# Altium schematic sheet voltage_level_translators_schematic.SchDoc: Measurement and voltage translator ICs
size A2; DocumentNumber: 4; SheetNumber: 4; SheetTotal: 8
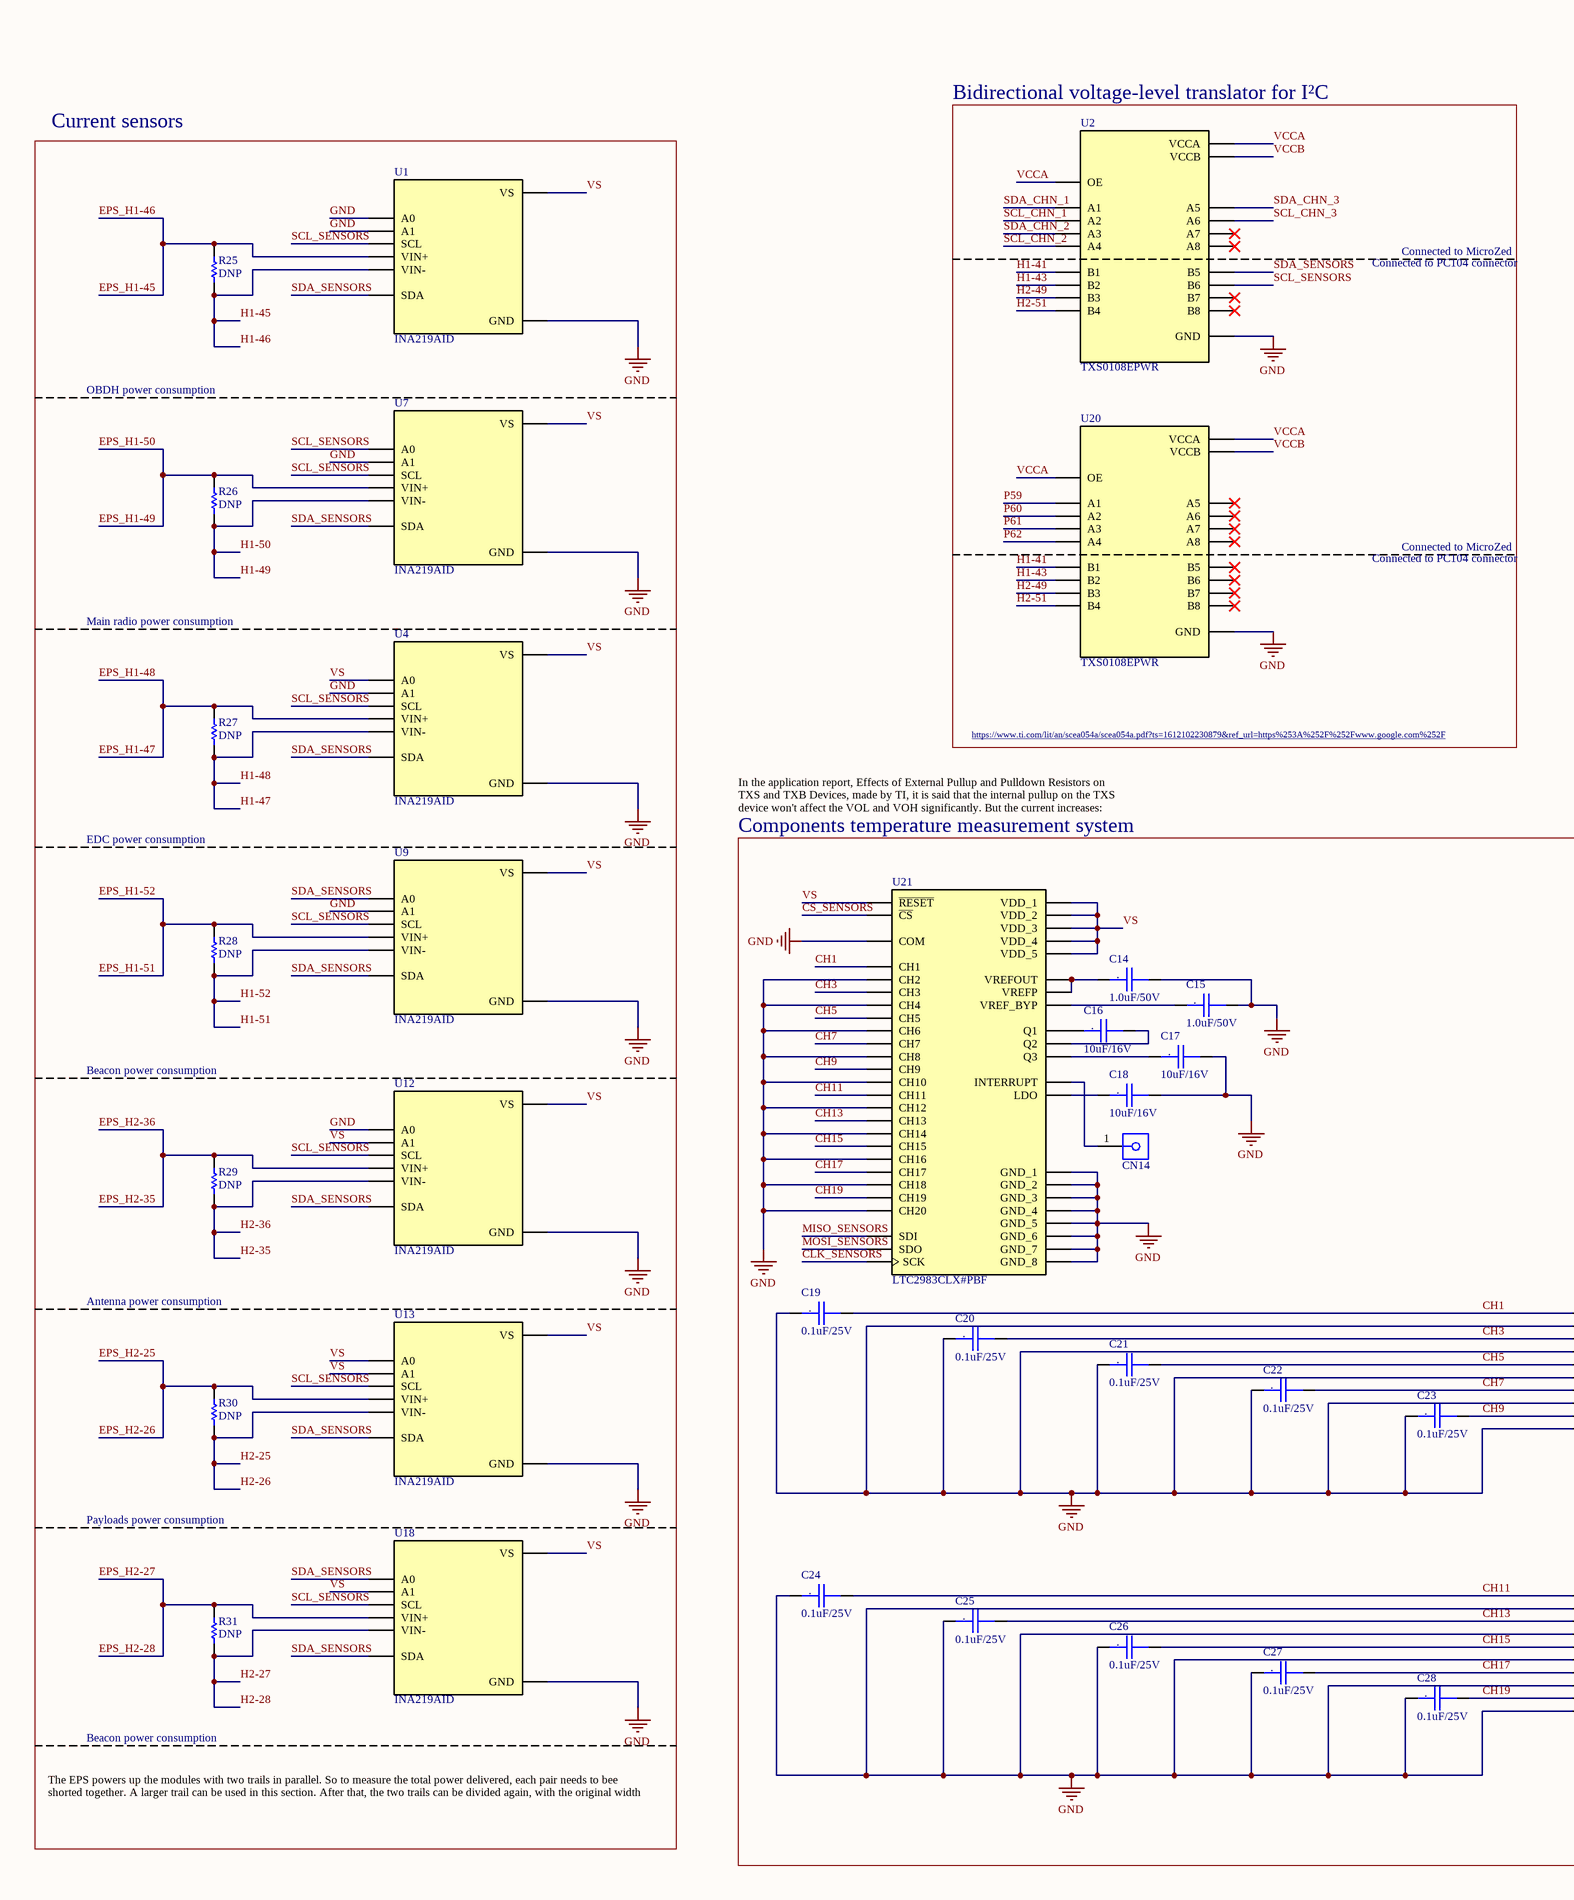
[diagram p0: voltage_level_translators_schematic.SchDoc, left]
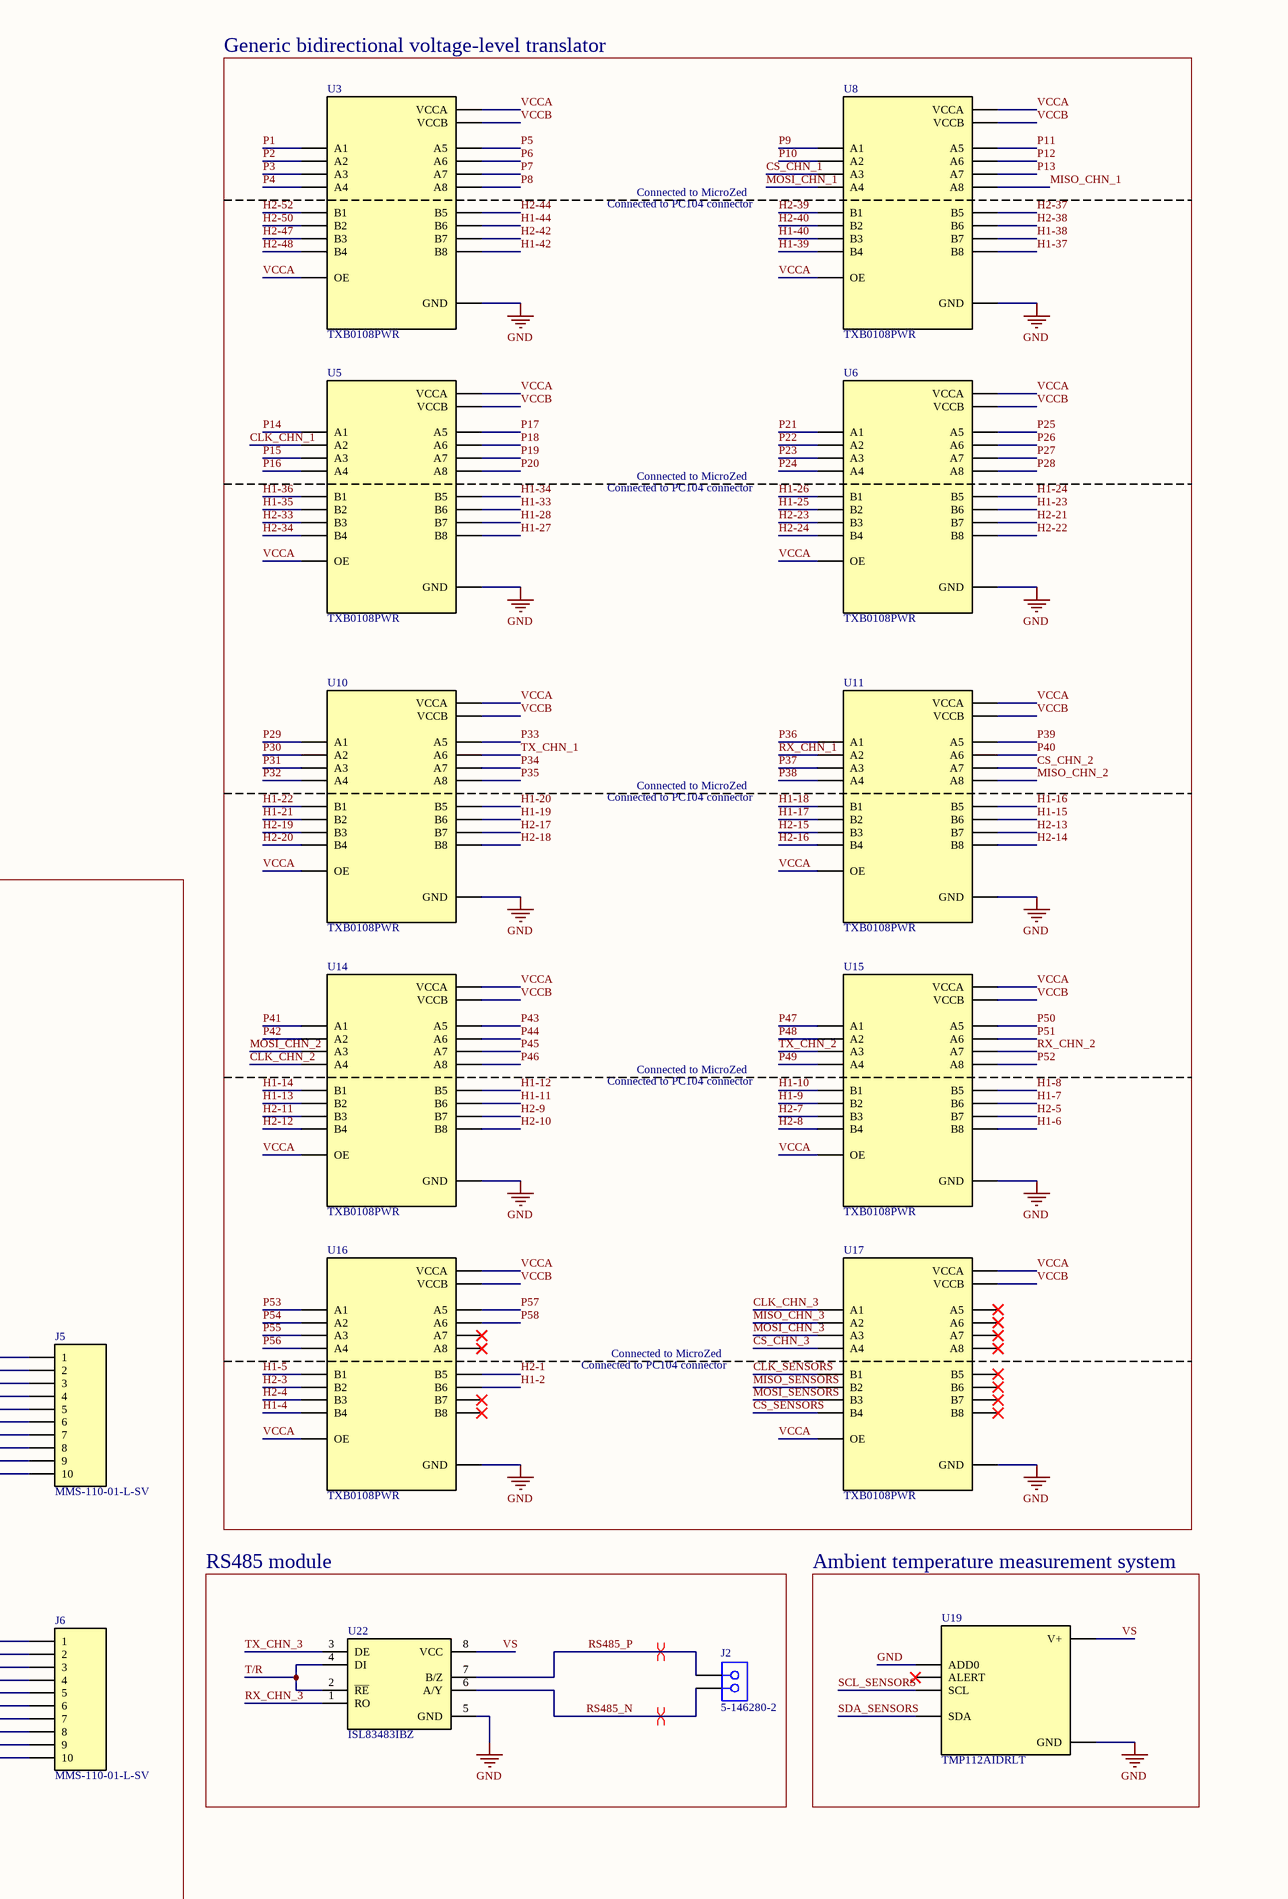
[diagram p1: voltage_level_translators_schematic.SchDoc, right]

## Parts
C14  1.0uF/50V  [CC0805]
C15  1.0uF/50V  [CC0805]
C16  10uF/16V  [CC1210]
C17  10uF/16V  [CC1210]
C18  10uF/16V  [CC1210]
C19  0.1uF/25V  [CC0805]
C20  0.1uF/25V  [CC0805]
C21  0.1uF/25V  [CC0805]
C22  0.1uF/25V  [CC0805]
C23  0.1uF/25V  [CC0805]
C24  0.1uF/25V  [CC0805]
C25  0.1uF/25V  [CC0805]
C26  0.1uF/25V  [CC0805]
C27  0.1uF/25V  [CC0805]
C28  0.1uF/25V  [CC0805]
CN14  TSW-101-05-T-S  [PIN BAR 1 2.54mm 180 GRAUS - Hide]  (value not drawn)
J2  5-146280-2  [PIN BAR 2 2.54mm 180 GRAUS]
J5  MMS-110-01-L-SV  [SAMTEC_MMS-110-01-L-SV]
J6  MMS-110-01-L-SV  [SAMTEC_MMS-110-01-L-SV]
R25  DNP  [0805]
R26  DNP  [0805]
R27  DNP  [0805]
R28  DNP  [0805]
R29  DNP  [0805]
R30  DNP  [0805]
R31  DNP  [0805]
U1  INA219AID  [SOIC127P599X175-8N]
U2  TXS0108EPWR  [SOP65P640X120-20N]
U3  TXB0108PWR  [SOP65P640X120-20N]
U4  INA219AID  [SOIC127P599X175-8N]
U5  TXB0108PWR  [SOP65P640X120-20N]
U6  TXB0108PWR  [SOP65P640X120-20N]
U7  INA219AID  [SOIC127P599X175-8N]
U8  TXB0108PWR  [SOP65P640X120-20N]
U9  INA219AID  [SOIC127P599X175-8N]
U10  TXB0108PWR  [SOP65P640X120-20N]
U11  TXB0108PWR  [SOP65P640X120-20N]
U12  INA219AID  [SOIC127P599X175-8N]
U13  INA219AID  [SOIC127P599X175-8N]
U14  TXB0108PWR  [SOP65P640X120-20N]
U15  TXB0108PWR  [SOP65P640X120-20N]
U16  TXB0108PWR  [SOP65P640X120-20N]
U17  TXB0108PWR  [SOP65P640X120-20N]
U18  INA219AID  [SOIC127P599X175-8N]
U19  TMP112AIDRLT  [SOT50P160X60-6N]
U20  TXS0108EPWR  [SOP65P640X120-20N]
U21  LTC2983CLX#PBF  [QFP50P900X900X160-48N]
U22  ISL83483IBZ  [SOIC127P600X175-8N]

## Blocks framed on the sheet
Generic bidirectional voltage-level translator: U3 U5 U6 U8 U10 U11 U14-U17
Bidirectional voltage-level translator for I²C: U2 U20
Current sensors: R25-R31 U1 U4 U7 U9 U12 U13 U18
Components temperature measurement system: C14-C28 CN14 J5 J6 U21
RS485 module: J2 U22
Ambient temperature measurement system: U19

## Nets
GND: C14.2 C15.2 C17.2 C18.2 C19.1 C20.1 C21.1 C22.1 C23.1 C24.1 C25.1 C26.1 C27.1 C28.1 J5.2 J5.4 J5.6 J5.8 J5.10 J6.2 J6.4 J6.6 J6.8 J6.10 U1.1(A1) U1.2(A0) U1.6(GND) U2.11(GND) U3.11(GND) U4.1(A1) U4.6(GND) U5.11(GND) U6.11(GND) U7.1(A1) U7.6(GND) U8.11(GND) U9.1(A1) U9.6(GND) U10.11(GND) U11.11(GND) U12.2(A0) U12.6(GND) U13.6(GND) U14.11(GND) U15.11(GND) U16.11(GND) U17.11(GND) U18.6(GND) U19.2(GND) U19.4(ADD0) U20.11(GND) U21.1(GND_1) U21.3(GND_2) U21.5(GND_3) U21.7(GND_4) U21.9(GND_5) U21.12(GND_6) U21.15(GND_7) U21.17(CH2) U21.19(CH4) U21.21(CH6) U21.23(CH8) U21.25(CH10) U21.27(CH12) U21.29(CH14) U21.31(CH16) U21.33(CH18) U21.35(CH20) U21.36(COM) U21.44(GND_8) U22.5(GND)
CH1: C19.2 J5.1 U21.16(CH1)
CH3: C20.2 J5.3 U21.18(CH3)
CH5: C21.2 J5.5 U21.20(CH5)
CH7: C22.2 J5.7 U21.22(CH7)
CH9: C23.2 J5.9 U21.24(CH9)
CH11: C24.2 J6.1 U21.26(CH11)
CH13: C25.2 J6.3 U21.28(CH13)
CH15: C26.2 J6.5 U21.30(CH15)
CH17: C27.2 J6.7 U21.32(CH17)
CH19: C28.2 J6.9 U21.34(CH19)
CLK_CHN_1: U5.3(A2)
CLK_CHN_2: U14.5(A4)
CLK_CHN_3: U17.1(A1)
CLK_SENSORS: U17.20(B1) U21.38(SCK)
CS_CHN_1: U8.4(A3)
CS_CHN_2: U11.8(A7)
CS_CHN_3: U17.5(A4)
CS_SENSORS: U17.16(B4) U21.41(~{CS})
EPS_H1-45: R25.1 U1.8(VIN+)  [also labelled EPS_H1-46]
EPS_H1-47: R27.1 U4.8(VIN+)  [also labelled EPS_H1-48]
EPS_H1-49: R26.1 U7.8(VIN+)  [also labelled EPS_H1-50]
EPS_H1-51: R28.1 U9.8(VIN+)  [also labelled EPS_H1-52]
EPS_H2-25: R30.1 U13.8(VIN+)  [also labelled EPS_H2-26]
EPS_H2-27: R31.1 U18.8(VIN+)  [also labelled EPS_H2-28]
EPS_H2-35: R29.1 U12.8(VIN+)  [also labelled EPS_H2-36]
H1-2: U16.14(B6)
H1-4: U16.16(B4)
H1-5: U16.20(B1)
H1-6: U15.12(B8)
H1-7: U15.14(B6)
H1-8: U15.15(B5)
H1-9: U15.18(B2)
H1-10: U15.20(B1)
H1-11: U14.14(B6)
H1-12: U14.15(B5)
H1-13: U14.18(B2)
H1-14: U14.20(B1)
H1-15: U11.14(B6)
H1-16: U11.15(B5)
H1-17: U11.18(B2)
H1-18: U11.20(B1)
H1-19: U10.14(B6)
H1-20: U10.15(B5)
H1-21: U10.18(B2)
H1-22: U10.20(B1)
H1-23: U6.14(B6)
H1-24: U6.15(B5)
H1-25: U6.18(B2)
H1-26: U6.20(B1)
H1-27: U5.12(B8)
H1-28: U5.13(B7)
H1-33: U5.14(B6)
H1-34: U5.15(B5)
H1-35: U5.18(B2)
H1-36: U5.20(B1)
H1-37: U8.12(B8)
H1-38: U8.13(B7)
H1-39: U8.16(B4)
H1-40: U8.17(B3)
H1-41: U2.20(B1) U20.20(B1)
H1-42: U3.12(B8)
H1-43: U2.18(B2) U20.18(B2)
H1-44: U3.14(B6)
H1-45: R25.2 U1.7(VIN-)  [also labelled H1-46]
H1-47: R27.2 U4.7(VIN-)  [also labelled H1-48]
H1-49: R26.2 U7.7(VIN-)  [also labelled H1-50]
H1-51: R28.2 U9.7(VIN-)  [also labelled H1-52]
H2-1: U16.15(B5)
H2-3: U16.18(B2)
H2-4: U16.17(B3)
H2-5: U15.13(B7)
H2-7: U15.17(B3)
H2-8: U15.16(B4)
H2-9: U14.13(B7)
H2-10: U14.12(B8)
H2-11: U14.17(B3)
H2-12: U14.16(B4)
H2-13: U11.13(B7)
H2-14: U11.12(B8)
H2-15: U11.17(B3)
H2-16: U11.16(B4)
H2-17: U10.13(B7)
H2-18: U10.12(B8)
H2-19: U10.17(B3)
H2-20: U10.16(B4)
H2-21: U6.13(B7)
H2-22: U6.12(B8)
H2-23: U6.17(B3)
H2-24: U6.16(B4)
H2-25: R30.2 U13.7(VIN-)  [also labelled H2-26]
H2-27: R31.2 U18.7(VIN-)  [also labelled H2-28]
H2-33: U5.17(B3)
H2-34: U5.16(B4)
H2-35: R29.2 U12.7(VIN-)  [also labelled H2-36]
H2-37: U8.15(B5)
H2-38: U8.14(B6)
H2-39: U8.20(B1)
H2-40: U8.18(B2)
H2-42: U3.13(B7)
H2-44: U3.15(B5)
H2-47: U3.17(B3)
H2-48: U3.16(B4)
H2-49: U2.17(B3) U20.17(B3)
H2-50: U3.18(B2)
H2-51: U2.16(B4) U20.16(B4)
H2-52: U3.20(B1)
MISO_CHN_1: U8.9(A8)
MISO_CHN_2: U11.9(A8)
MISO_CHN_3: U17.3(A2)
MISO_SENSORS: U17.18(B2) U21.40(SDI)
MOSI_CHN_1: U8.5(A4)
MOSI_CHN_2: U14.4(A3)
MOSI_CHN_3: U17.4(A3)
MOSI_SENSORS: U17.17(B3) U21.39(SDO)
P1: U3.1(A1)
P2: U3.3(A2)
P3: U3.4(A3)
P4: U3.5(A4)
P5: U3.6(A5)
P6: U3.7(A6)
P7: U3.8(A7)
P8: U3.9(A8)
P9: U8.1(A1)
P10: U8.3(A2)
P11: U8.6(A5)
P12: U8.7(A6)
P13: U8.8(A7)
P14: U5.1(A1)
P15: U5.4(A3)
P16: U5.5(A4)
P17: U5.6(A5)
P18: U5.7(A6)
P19: U5.8(A7)
P20: U5.9(A8)
P21: U6.1(A1)
P22: U6.3(A2)
P23: U6.4(A3)
P24: U6.5(A4)
P25: U6.6(A5)
P26: U6.7(A6)
P27: U6.8(A7)
P28: U6.9(A8)
P29: U10.1(A1)
P30: U10.3(A2)
P31: U10.4(A3)
P32: U10.5(A4)
P33: U10.6(A5)
P34: U10.8(A7)
P35: U10.9(A8)
P36: U11.1(A1)
P37: U11.4(A3)
P38: U11.5(A4)
P39: U11.6(A5)
P40: U11.7(A6)
P41: U14.1(A1)
P42: U14.3(A2)
P43: U14.6(A5)
P44: U14.7(A6)
P45: U14.8(A7)
P46: U14.9(A8)
P47: U15.1(A1)
P48: U15.3(A2)
P49: U15.5(A4)
P50: U15.6(A5)
P51: U15.7(A6)
P52: U15.9(A8)
P53: U16.1(A1)
P54: U16.3(A2)
P55: U16.4(A3)
P56: U16.5(A4)
P57: U16.6(A5)
P58: U16.7(A6)
P59: U20.1(A1)
P60: U20.3(A2)
P61: U20.4(A3)
P62: U20.5(A4)
RS485_N: J2.2 U22.6(A/Y)
RS485_P: J2.1 U22.7(B/Z)
RX_CHN_1: U11.3(A2)
RX_CHN_2: U15.8(A7)
RX_CHN_3: U22.1(RO)
SCL_CHN_1: U2.3(A2)
SCL_CHN_2: U2.5(A4)
SCL_CHN_3: U2.7(A6)
SCL_SENSORS: U1.4(SCL) U2.14(B6) U4.4(SCL) U7.2(A0) U7.4(SCL) U9.4(SCL) U12.4(SCL) U13.4(SCL) U18.4(SCL) U19.1(SCL)
SDA_CHN_1: U2.1(A1)
SDA_CHN_2: U2.4(A3)
SDA_CHN_3: U2.6(A5)
SDA_SENSORS: U1.3(SDA) U2.15(B5) U4.3(SDA) U7.3(SDA) U9.2(A0) U9.3(SDA) U12.3(SDA) U13.3(SDA) U18.2(A0) U18.3(SDA) U19.6(SDA)
T/R: U22.2(~{RE}) U22.4(DI)
TX_CHN_1: U10.7(A6)
TX_CHN_2: U15.4(A3)
TX_CHN_3: U22.3(DE)
VCCA: U2.2(VCCA) U2.10(OE) U3.2(VCCA) U3.10(OE) U5.2(VCCA) U5.10(OE) U6.2(VCCA) U6.10(OE) U8.2(VCCA) U8.10(OE) U10.2(VCCA) U10.10(OE) U11.2(VCCA) U11.10(OE) U14.2(VCCA) U14.10(OE) U15.2(VCCA) U15.10(OE) U16.2(VCCA) U16.10(OE) U17.2(VCCA) U17.10(OE) U20.2(VCCA) U20.10(OE)
VCCB: U2.19(VCCB) U3.19(VCCB) U5.19(VCCB) U6.19(VCCB) U8.19(VCCB) U10.19(VCCB) U11.19(VCCB) U14.19(VCCB) U15.19(VCCB) U16.19(VCCB) U17.19(VCCB) U20.19(VCCB)
VS: U1.5(VS) U4.2(A0) U4.5(VS) U7.5(VS) U9.5(VS) U12.1(A1) U12.5(VS) U13.1(A1) U13.2(A0) U13.5(VS) U18.1(A1) U18.5(VS) U19.5(V+) U21.2(VDD_1) U21.4(VDD_2) U21.6(VDD_3) U21.8(VDD_4) U21.42(~{RESET}) U21.45(VDD_5) U22.8(VCC)
NetC14_1: C14.1 U21.13(VREFOUT) U21.14(VREFP)
NetC15_1: C15.1 U21.11(VREF_BYP)
NetC16_1: C16.1 U21.48(Q1)
NetC16_2: C16.2 U21.47(Q2)
NetC17_1: C17.1 U21.46(Q3)
NetC18_1: C18.1 U21.43(LDO)
NetCN14_1: CN14.1 U21.37(INTERRUPT)

Not connected (* = marked no-connect by the designer): U2 8(A7)* 9(A8)* 12(B8)* 13(B7)*; U16 8(A7)* 9(A8)* 12(B8)* 13(B7)*; U17 6(A5)* 7(A6)* 8(A7)* 9(A8)* 12(B8)* 13(B7)* 14(B6)* 15(B5)*; U19 3(ALERT)*; U20 6(A5)* 7(A6)* 8(A7)* 9(A8)* 12(B8)* 13(B7)* 14(B6)* 15(B5)*

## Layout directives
differential pair: RS485_N, RS485_P

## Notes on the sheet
- Connected to PC104 connector
- Connected to MicroZed
- OBDH power consumption
- Main radio power consumption
- https://www.ti.com/lit/an/scea054a/scea054a.pdf?ts=1612102230879&ref_url=https%253A%252F%252Fwww.google.com%252F
- In the application report, Effects of External Pullup and Pulldown Resistors on TXS and TXB Devices, made by TI, it is said that the internal pullup on the TXS device won't affect the VOL and VOH significantly. But the current increases:
- EDC power consumption
- Beacon power consumption
- Antenna power consumption
- Payloads power consumption
- The EPS powers up the modules with two trails in parallel. So to measure the total power delivered, each pair needs to bee shorted together. A larger trail can be used in this section. After that, the two trails can be divided again, with the original width

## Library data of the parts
C14 C15 = Cap_Cer_X7R_1.0uF_50V_0805: CAP CER 1.0uF 50V 10% X7R 0805; Manufacturer Part Number: C0805X105K5RACAUTO
C16-C18 = Cap_Cer_X7R_10uF_16V_1210: CAP CER 10uF 16V 10% X7R 1210; Manufacturer Part Number: C1210C106K4RACTU
C19-C28 = Cap_Cer_X7R_0.1uF_25V_0805: CAP CER 0.1uF 25V 10% X7R 0805; Manufacturer Part Number: CC0805KRX7R8BB104
CN14 = TSW-101-05-T-S: CONN HEADER 1POS .100" SNGL TIN; Manufacturer: Samtec Inc; N of Positions: 2; Pitch: 2.54mm
J2 = 5-146280-2: 02 MODII HDR SRST B/A .100CL; MF: TE Connectivity; Product_Type: Connector; Number_of_Positions: 2; Centerline_Pitch: 2.54 mm[.1 in]
J5 J6 = MMS-110-01-L-SV: Conn Socket Strip SKT 10 POS 2mm Solder ST Thru-Hole Tube
R25-R31 = RDNP_0805: RES DNP 0805; Manufacturer Part Number: UR73V2ATTD47L0F
U1 U4 U7 U9 U12 U13 U18 = INA219AID: 26V, 12-bit, i2c output current/voltage/power monitor 8-SOIC -40 to 125; MF: Texas Instruments
U2 U20 = TXS0108EPWR: 8-Bit Bidirectional Voltage-Level Shifter For Open-Drain And Push-Pull Application; MF: Texas Instruments
U3 U5 U6 U8 U10 U11 U14-U17 = TXB0108PWR: 8-Bit Bidirectional Voltage-Level Shifter with Auto Direction Sensing and +/-15-kV ESD Protect 20-TSSOP -40 to 85; MF: Texas Instruments
U19 = TMP112AIDRLT: 0.5C 1.4V to 3.6V digital temperature sensor with I2C/SMBus in 2.56mm2 package 6-SOT-5X3 -40 to 125; MF: Texas Instruments
U21 = LTC2983CLX#PBF: IC SENSOR THERMAL; MF: Analog Devices
U22 = ISL83483IBZ: 1/1 Transceiver Half RS422, RS485 8-SOIC; Manufacturer Part Number: ISL83483IBZ-T; MF: Renesas Electronics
